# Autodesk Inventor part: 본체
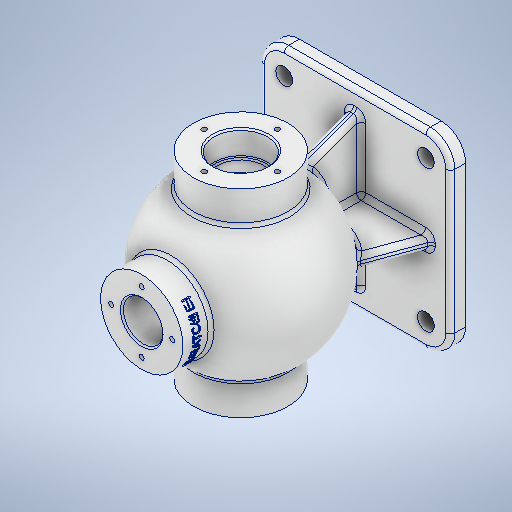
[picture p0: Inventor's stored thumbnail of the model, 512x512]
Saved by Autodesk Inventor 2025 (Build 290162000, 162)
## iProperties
Created: 2025-08
Part Number: 본체
Material: 알루미늄 6061
Document SubType Name: Sheet Metal
Designer: infra02
Density: 2.7 g/cm^3
Sheet Metal Rule: 기본값_mm
Appearance: 알루미늄 - 평지
Mass: 1526.65 g
Surface Area: 1172.5 cm^2
Volume: 565.426 cm^3
Author: infra02
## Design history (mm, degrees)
sketch "스케치1"
  geometry: L1 (-62.5, 62.5)-(62.5, 62.5); L2 (62.5, 62.5)-(62.5, -62.5); L3 (62.5, -62.5)-(-62.5, -62.5); L4 (-62.5, -62.5)-(-62.5, 62.5); L5 (-62.5, 62.5)-(62.5, -62.5); L6 (62.5, 62.5)-(-62.5, -62.5); L7 (-46.5, 46.5)-(46.5, 46.5); L8 (46.5, 46.5)-(46.5, -46.5); L9 (46.5, -46.5)-(-46.5, -46.5); L10 (-46.5, -46.5)-(-46.5, 46.5); L11 (-46.5, 46.5)-(46.5, -46.5); L12 (46.5, 46.5)-(-46.5, -46.5); C1 r 5.5 at (-46.5, 46.5); C2 r 5.5 at (46.5, 46.5); C3 r 5.5 at (-46.5, -46.5); C4 r 5.5 at (46.5, -46.5); 5 further points
  constraints: 24 end point, 7 coincident, 4 centre point, 4 midpoint, 4 parallel, 2 horizontal, 2 perpendicular, 1 point on line
  dimensions: "d0" = 125 distance of L2.end L3.end; "d1" = 125 distance of L1.end L2.end; "d2" = 93 distance of L8.end L9.end; "d3" = 93 distance of L7.end L8.end; "d4" = 11 diameter of C1; "d5" = 11 diameter of C2; "d6" = 11 diameter of C3; "d7" = 11 diameter of C4; "d8" = 16 distance from line of L4 C3.centre
extrude "돌출1" new body sketch "스케치1" stored distance "d9" = 10; taper "d10" = 0 deg
node "작업 평면1"
sketch "스케치3"
  geometry: L1 (0, 54)-(0, -54); A1 r 54 centre (0, 0) between (0, 54) and (0, -54); 1 further point
  constraints: 2 end point, 2 point on circle, 1 centre point, 1 coincident, 1 vertical
  dimensions: "d12" = 108 diameter of A1; "d13" = 108 distance of L1.start L1.end
revolve "회전1" sketch "스케치3" stored, may be unused: angle "d14" = 90 deg
sketch "스케치5"
  geometry: L1 (-62.5, -5)-(-62.5, 5) reference; L2 (62.5, 5)-(-62.5, 5) reference; L3 (62.5, 5)-(62.5, -5) reference; L4 (-62.5, -5)-(62.5, -5) reference; L5 (62.5, 5)-(-62.5, 5) reference; L6 (50.5, 5)-(30.869, 58.937); L7 (-50.5, 5)-(-30.789, 59.154); L8 (50.5, 5)-(-50.5, 5); L9 (30.869, 58.937)-(-30.869, 58.937); 3 further points
  constraints: 8 end point, 3 point on line, 1 collinear, 1 parallel
  dimensions: "d15" = 20 deg angle of L6 L3; "d16" = 20 deg angle of L1 L7; "d17" = 12 distance of L6.start L2.start; "d18" = 12 distance of L1.end L7.start
extrude "돌출2" join sketch "스케치5" stored distance "d19" = 8; taper "d20" = 0 deg
sketch "스케치6"
  geometry: L1 (62.5, -5)-(62.5, 5) reference; L2 (-62.5, 5)-(62.5, 5) reference; L3 (-62.5, -5)-(-62.5, 5) reference; L4 (62.5, -5)-(-62.5, -5) reference; L5 (-50.5, 5)-(-30.386, 60.262); L6 (52, 5)-(52, -5) reference; L7 (50.5, 5)-(26.621, 70.608); L8 (50.5, 5)-(-50.5, 5); L9 (26.621, 70.608)-(-26.621, 70.608); L10 (-26.621, 70.608)-(-37.385, 41.034); A1 r 54 centre (0, 80) between (4, 26.148) and (-4, 26.148) reference; 3 further points
  constraints: 10 end point, 2 point on line, 1 horizontal, 1 point on circle
  dimensions: "d21" = 20 deg angle of L3 L5; "d23" = 12 distance of L5.start L2.start; "d24" = 12 distance of L7.start L1.end; "d25" = 0 distance from line of L2 L7.start; "d26" = 20 deg angle of L7 L1
extrude "돌출3" join sketch "스케치6" stored distance "d27" = 8; taper "d28" = 0 deg
node "작업 평면2"
sketch "스케치9"
  geometry: L1 (-4, 41.186)-(-4, 26.297) reference; L2 (-37.329, 41.186)-(-37.329, 41.186) reference; L3 (-4, 26.297)-(-4, 41.186) reference; L4 (4, 41.186)-(4, 26.297) reference; L5 (37.329, 41.186)-(37.329, 41.186) reference; L6 (4, 26.297)-(4, 41.186) reference; C1 r 31 at (0, 80); A1 r 53.852 centre (0, 80) between (-37.329, 41.186) and (-4, 26.297) reference; A2 r 53.852 centre (0, 80) between (-37.329, 41.186) and (-4, 26.297) reference; A3 r 53.852 centre (0, 80) between (4, 26.297) and (37.329, 41.186) reference; A4 r 53.852 centre (0, 80) between (4, 26.297) and (37.329, 41.186) reference; 3 further points; 2 other entities
  constraints: 1 centre point, 1 coincident, 2 other
  dimensions: "d30" = 62 diameter of C1
extrude "돌출4" join sketch "스케치9" distance "d31" = 15; taper "d32" = 0 deg
feature "면 삭제1"
feature "면 삭제2"
node "작업 평면3"
sketch "스케치10"
  geometry: C1 r 27 at (0, 0); 1 further point
  constraints: 1 centre point, 1 coincident
  dimensions: "d34" = 54 diameter of C1
extrude "돌출5" join sketch "스케치10" distance "d35" = 20; taper "d36" = 0 deg
sketch "스케치11"
  geometry: C1 r 13 at (0, 0); 1 further point
  constraints: 1 centre point, 1 coincident
  dimensions: "d37" = 26 diameter of C1
extrude "돌출6" cut sketch "스케치11" distance "d38" = 35.5; taper "d39" = 0 deg
sketch "스케치12"
  geometry: C1 r 17.5 at (0, 0); C2 r 31 at (0, 0) reference; 1 further point
  constraints: 1 centre point, 1 concentric
  dimensions: "d40" = 35 diameter of C1
extrude "돌출7" cut sketch "스케치12" distance "d41" = 155; taper "d42" = 0 deg
sketch "스케치16"
  geometry: L1 (65, 97.5)-(65, 62.5) reference; L2 (65, 80)-(-65, 80); L3 (-65, 62.5)-(-65, 97.5) reference; L4 (65, 80)-(49, 80); L5 (65, 97.5)-(-65, 97.5) reference; L6 (49, 80)-(49, 95); L7 (49, 95)-(28.624, 95); L8 (28.624, 95)-(28.624, 80); L9 (47.915, 80)-(28.624, 80); L10 (49, 95)-(28.624, 95); L11 (28.624, 95)-(28.624, 97.5); L12 (28.624, 97.5)-(49, 97.5); L13 (49, 97.5)-(49, 95); 3 further points
  constraints: 20 end point, 5 point on line, 3 perpendicular, 2 horizontal, 2 midpoint, 2 parallel, 1 collinear
  dimensions: "d65" = 16 distance of L2.start L4.end; "d66" = 15 distance of L4.end L6.end; "d67" = 20.3763 distance between parallel lines of L6 L8
revolve "회전3" sketch "스케치16" stored, may be unused: angle "d68" = 90 deg
sketch "스케치13"
  geometry: L1 (-27, 126.765)-(27, 126.765) reference; L2 (-44.215, 49)-(-44.215, 111) reference; L3 (44.215, 111)-(44.215, 49) reference; L4 (-4, 26.297)-(-4, 41.186) reference; L5 (4, 41.186)-(4, 26.297) reference; L6 (37.329, 41.186)-(37.329, 41.186) reference; L7 (4, 26.297)-(4, 41.186) reference; L8 (-4, 41.186)-(-4, 26.297) reference; L9 (-37.329, 41.186)-(-37.329, 41.186) reference; L10 (-44, 80)-(44, 80); L11 (-65, 49)-(-65, 111) reference; L12 (88, 80)-(-90.5, 80) reference; A1 r 53.852 centre (0, 80) between (-37.329, 41.186) and (-4, 26.297) reference; A2 r 53.852 centre (0, 80) between (4, 26.297) and (37.329, 41.186) reference; A3 r 53.852 centre (0, 80) between (4, 26.297) and (37.329, 41.186) reference; A4 r 53.852 centre (0, 80) between (-37.329, 41.186) and (-4, 26.297) reference; A5 r 44 centre (0, 80) between (-44, 80) and (44, 80); 4 further points; 2 other entities
  constraints: 2 end point, 2 point on circle, 1 centre point, 1 coincident, 1 midpoint, 1 perpendicular, 1 point on line, 2 other
  dimensions: "d43" = 88 diameter of A5
revolve "회전2" sketch "스케치13" stored, may be unused: angle "d44" = 90 deg
sketch "스케치14"
  geometry: C1 r 31 at (0, 0) reference; A1 r 24 centre (0, 0) between (0, 24) and (-24, 0); 3 further points
  constraints: 4 point on circle, 1 centre point, 1 concentric
  dimensions: "d45" = 48 diameter of A1
hole "구멍1" sketch "스케치14" at (0, 24), (-24, 0), (0, -24), (24, 0) diameter "d46" = 3.242; stored, may be unused: countersink angle "d50" = 90 deg, drill point angle "d52" = 118 deg; dims "d47" = 12, "d48" = 4, "d49" = 2, "d51" = 15
sketch "스케치15"
  geometry: L1 (15, -41.364)-(-15, -41.364) reference; L2 (-15, 41.364)-(15, 41.364) reference; C1 r 13 at (0, 0) reference; A1 r 20 centre (0, 0) between (20, 0) and (0, 20); 3 further points
  constraints: 4 point on circle, 1 centre point, 1 coincident
  dimensions: "d53" = 40 diameter of A1
hole "구멍2" sketch "스케치15" at (20, 0), (0, 20), (-20, 0), (0, -20) diameter "d54" = 3.242; stored, may be unused: countersink angle "d58" = 90 deg, drill point angle "d60" = 118 deg; dims "d55" = 9, "d56" = 4, "d57" = 2, "d59" = 11
fillet "모깎기1" dims "d61" = 3
fillet "모깎기2" dims "d62" = 3
fillet "모깎기3" dims "d63" = 16
fillet "모깎기4" dims "d64" = 3
fillet "모깎기5" dims "d69" = 3
chamfer "모따기1" distance "d70" = 1; stored, may be unused: second distance "d71" = 2, angle "d72" = 45 deg
chamfer "모따기2" distance "d73" = 1; stored, may be unused: second distance "d74" = 2, angle "d75" = 45 deg
fillet "모깎기6" dims "d76" = 0.6
chamfer "모따기3" distance "d77" = 1; stored, may be unused: second distance "d78" = 2, angle "d79" = 45 deg
fillet "모깎기7" dims "d80" = 0.6
fillet "모깎기8" dims "d81" = 3
node "작업 평면5"
sketch "스케치17"
  geometry: L1 (-14.282, 140.462)-(14.449, 140.462); L2 (14.449, 140.462)-(14.449, 131.538); L3 (14.449, 131.538)-(-14.282, 131.538); L4 (-14.282, 131.538)-(-14.282, 140.462); L5 (-27, 145)-(27, 145) reference; 2 further points
  constraints: 1 midpoint, 2 other
  dimensions: "d86" = 9 distance from line of L5 point (14.449, 136)
feature "엠보싱2" sketch "스케치17" dims "d87" = 0.5, "d88" = 0, "CornerReliefSize" = 2 (derived)
feature "Ќ耀Ў耀А耀В耀Д耀Ж耀И耀К耀" dims "d0" = 125, "d1" = 125, "d2" = 93, "d3" = 93, "d4" = 11, "d5" = 11, "d6" = 11, "d7" = 11, "d8" = 16, "d9" = 10, "d10" = 0, "d11" = -85, "d12" = 108, "d13" = 108, "d14" = 90 deg, "d15" = 20 deg, "d16" = 20 deg, "d17" = 12, "d18" = 12, "d19" = 8, "d20" = 0, "d21" = 20 deg, "d23" = 12, "d24" = 12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
node "솔리드1"
mirror "미러1"
mirror "미러3"
mirror "미러2"
node "투영된 루프1"
node "투영된 루프2"
node "투영된 루프4"
node "투영된 루프5"
node "투영된 루프6"
feature "A9D066F2-1C7D-4E18-AEED-F7BC21143FA4" dims "d46" = 3.242, "d47" = 12, "d48" = 4, "d49" = 2, "d50" = 90 deg, "d51" = 15, "d52" = 118 deg
